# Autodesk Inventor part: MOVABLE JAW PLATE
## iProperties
Created: 2006-07
Part Number: MOVABLE JAW PLATE
Material: Steel, Mild
Document SubType Name: Modeling
Designer: rollin42
Density: 7.86 g/cm^3
Author: rollin42
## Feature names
1. Extrusion1
2. Hole1
3. Rectangular Pattern1
